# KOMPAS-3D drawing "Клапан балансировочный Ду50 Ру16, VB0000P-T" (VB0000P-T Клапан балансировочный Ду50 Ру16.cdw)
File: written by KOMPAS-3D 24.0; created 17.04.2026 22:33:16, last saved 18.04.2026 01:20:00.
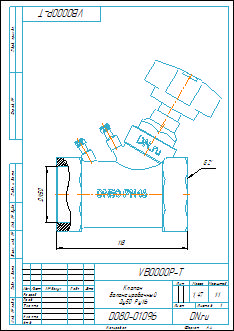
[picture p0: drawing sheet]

Document properties: Автор: tyuri; Форматы листов документа: A4; Полное имя файла: VB0000P-T Клапан балансировочный Ду50 Ру16.m3d; Масса: 1.47; Наименование: Клапан балансировочный Ду50 Ру16; Количество листов документа: 1; Примечание: D080-01096

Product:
- Body: Тело 2  | qty 1
    Масса: 2.729662
- Part/product: Клапан балансировочный Ду50 Ру16  | designation VB0000P-T
    Масса: 1.47
    Раздел спецификации: Прочие изделия
    Примечание: D080-01096

Views: Вид 1, Местный разрез 1, Справа
Referenced files in D:\Аутсорс\VB0000P-T Клапан балансировочный статический DN.ru\DN25\: VB0000P-T  Клапан балансировочный статический Ду25 Ру16.m3d
Referenced files in E:\Работа\Зайцев\АУТСОРС\Диман\Балансировка\VB0000P-T Клапан балансировочный DN.ru Ду15-50 Ру16\DN50\: VB0000P-T Клапан балансировочный Ду50 Ру16.m3d
Referenced files in D:\Аутсорс\VB0000P-T Клапан балансировочный статический DN.ru\DN20\: VB0000P-T  Клапан балансировочный статический Ду15 Ру16.cdw
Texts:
  VB0000P-T
  Клапан
  балансировочный
  Ду50 Ру16
  Клапан балансировочный Ду50 Ру16
  VB0000P-T Клапан балансировочный Ду50 Ру16
Dimensions and other numbers on the sheet: 0; 3; 2; 4; 50; 118; 1:1; 1; 1,47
